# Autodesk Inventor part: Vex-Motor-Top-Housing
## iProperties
Created: 2007-08
Part Number: Vex-Motor-Top-Housing
Material: Alloy Steel
Document SubType Name: Modeling
Density: 7.85 g/cm^3
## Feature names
1. Base1
